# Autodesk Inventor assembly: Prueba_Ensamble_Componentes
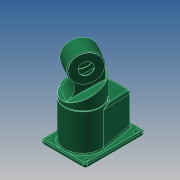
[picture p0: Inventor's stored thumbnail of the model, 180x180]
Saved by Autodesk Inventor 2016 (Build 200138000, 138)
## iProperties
Created: 2015-10
Part Number: Prueba_Ensamble_Componentes
Document SubType Name: Assembly
Designer: julian.chica
Author: julian.chica
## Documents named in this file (3)
- C:\Test ExamProfessor 2015\Prueba_Ensamble_Componentes.iam
- C:\Test ExamProfessor 2015\Robot-Base-Model-A.ipt
- C:\Test ExamProfessor 2015\Robot-Axis1-2.ipt
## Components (2 placed, 2 different names)
1. Robot-Base-Model-A:1 — Insert:1, Angle:1
2. Robot-Axis1-2:1 — Insert:1, Angle:1
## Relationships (2: Insert 1, Angle 1)
- Insert:1: Robot-Base-Model-A:1 ↔ Robot-Axis1-2:1
- Angle:1: Robot-Base-Model-A:1 ↔ Robot-Axis1-2:1
